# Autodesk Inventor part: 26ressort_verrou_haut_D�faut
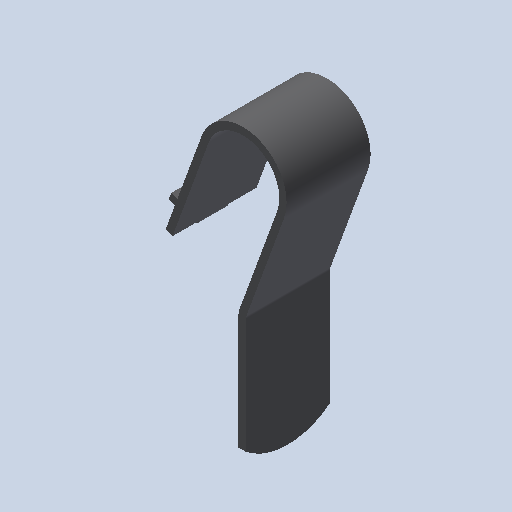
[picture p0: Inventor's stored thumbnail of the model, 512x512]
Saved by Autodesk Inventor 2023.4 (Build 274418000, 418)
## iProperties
Created: 2011-01
Part Number: 26ressort_verrou_haut_D�faut
Document SubType Name: Modeling
Designer: eric
Density: 1 g/cm^3
Mass: 0.756418 g
Surface Area: 16.7077 cm^2
Volume: 0.756418 cm^3
Material: Générique
Appearance: Red
Author: eric
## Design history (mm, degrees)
feature "Base1"
node "Corps solides"
node "Corps surfaciques"
node "Solide1"
